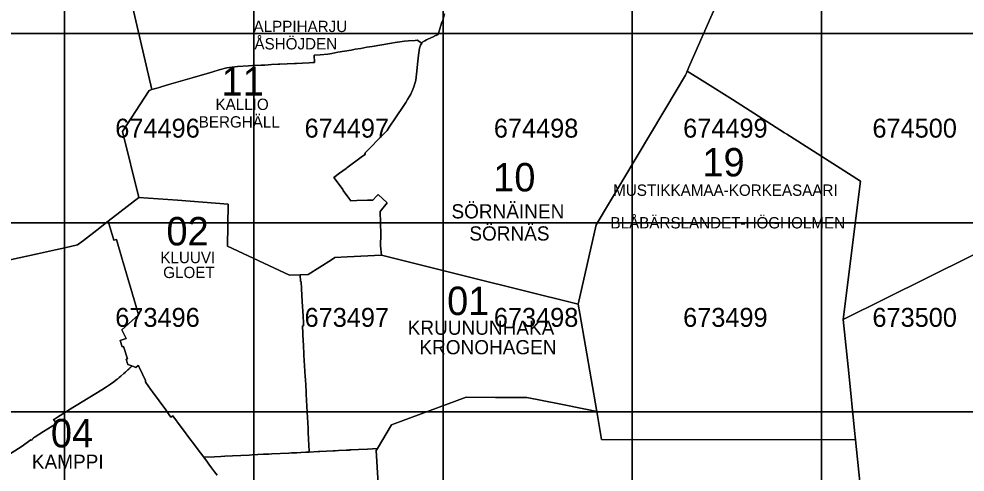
# Model space of a CAD drawing. Extents: x 25485000 to 25520000, y 6656775 to 6690000.
# Drawn here: x 25495760 to 25500758, y 6672682 to 6675077 of the extents above; entities that cross this region are included whole.
import ezdxf

# ---------------------------------------------------------------- set-up
doc = ezdxf.new("R2010")
doc.units = 0
doc.layers.add('Level 63', color=7, linetype='Continuous')

msp = doc.modelspace()

# ---------------------------------------------------------------- linework, layer by layer
at = {"layer": 'Level 63'}
for points in [[(25501089.3, 6676421.3), (25500427.3, 6676867.8), (25500377.3, 6676901.5), (25499887.6, 6676162.5), (25499782.6, 6675923.4), (25499559.7, 6675415.6), (25499304.6, 6674834.5), (25499290.4, 6674802.1), (25499383.4, 6674743.1), (25499528.4, 6674650.9), (25499804.3, 6674475.3), (25499816, 6674467.8), (25500077.8, 6674301.6), (25500206, 6674219.8), (25500113.5, 6673489.1), (25501011.9, 6673933.9)], [(25495704.9, 6673802), (25495858, 6673836.1), (25495952.7, 6673857.2), (25496001.9, 6673868.2), (25496069.3, 6673882.8), (25496101, 6673906.8), (25496170.3, 6673961.1), (25496230.7, 6674007.9), (25496393.6, 6674134.2), (25496307.3, 6674481.8), (25496447.8, 6674699.9), (25496462.5, 6674704.2), (25496263.6, 6675552.9)], [(25496263.6, 6675552.9), (25496462.5, 6674704.2), (25496507.4, 6674717.3), (25496511.4, 6674718.4), (25496551.1, 6674730), (25496674.6, 6674765.9), (25496692.2, 6674771.1), (25496749, 6674787.6), (25496783.5, 6674797.7), (25496818.1, 6674807.7), (25496858.7, 6674819.5), (25496885.4, 6674822.7), (25496914.1, 6674826.2), (25496972.5, 6674829.3), (25496993.7, 6674830.4), (25497009.8, 6674831.2), (25497039.8, 6674832.7), (25497057.8, 6674833.7), (25497093.2, 6674835.6), (25497128.7, 6674837.4), (25497138.7, 6674838), (25497215.1, 6674842), (25497225.2, 6674842.5), (25497258.1, 6674844.2), (25497292.4, 6674845.9), (25497312.4, 6674846.9), (25497321.4, 6674847.4), (25497319.5, 6674885.4), (25497351.2, 6674888.2), (25497391.9, 6674891.6), (25497411.7, 6674895.1), (25497445, 6674900.9), (25497480, 6674906.9), (25497515, 6674913), (25497536.6, 6674916.7), (25497566.2, 6674921.8), (25497597.7, 6674927.3), (25497626.3, 6674932.2), (25497727.2, 6674949.7), (25497748, 6674953), (25497772.2, 6674956.8), (25497795.7, 6674959.3), (25497817.8, 6674961.6), (25497853.5, 6674963.9), (25497863.4, 6674964.6), (25497887.7, 6674948.6), (25497890.6, 6674953), (25497892.8, 6674956.4), (25497903.2, 6674961.3), (25497913.1, 6674966.1), (25497920.4, 6674969.6), (25497947.3, 6674982.2), (25497954.6, 6674985.6), (25497953.9, 6674986.9), (25497963.9, 6674991.6), (25497964.5, 6674990.3), (25497973.7, 6674994.6), (25497980.4, 6675012), (25497992.1, 6675054.4), (25497999.1, 6675071.1), (25498008.1, 6675103.9)], [(25498008.1, 6675103.9), (25497999.1, 6675071.1), (25497992.1, 6675054.4), (25497980.4, 6675012), (25497973.7, 6674994.6), (25497964.5, 6674990.3), (25497963.9, 6674991.6), (25497953.9, 6674986.9), (25497954.6, 6674985.6), (25497947.3, 6674982.2), (25497920.4, 6674969.6), (25497913.1, 6674966.1), (25497903.2, 6674961.3), (25497892.8, 6674956.4), (25497890.6, 6674953), (25497887.7, 6674948.6), (25497881.1, 6674938.4), (25497874.9, 6674922.2), (25497871, 6674885.4), (25497867.6, 6674853.6), (25497863.9, 6674819.8), (25497861.8, 6674800.9), (25497856.8, 6674754.5), (25497853.1, 6674741.9), (25497846.2, 6674718.4), (25497842.5, 6674709.6), (25497829.7, 6674679.5), (25497812.1, 6674650.8), (25497802.7, 6674635.5), (25497792.7, 6674620.4), (25497749.2, 6674554.7), (25497716, 6674504.7), (25497704.1, 6674486.9), (25497690.7, 6674474.2), (25497585.4, 6674366.6), (25497590.2, 6674362.3), (25497567.8, 6674345.9), (25497491.9, 6674290.3), (25497487.9, 6674287.4), (25497452.4, 6674261.4), (25497423, 6674239.9), (25497440.6, 6674215.7), (25497470, 6674175.1), (25497473, 6674171.1), (25497502.6, 6674130.2), (25497512.9, 6674116), (25497545.4, 6674117), (25497600.2, 6674118.6), (25497629.8, 6674119.5), (25497649.4, 6674141.2), (25497651.6, 6674143.7), (25497657.4, 6674150.2), (25497705.7, 6674105.6), (25497668.4, 6674059.8), (25497672.2, 6673938.9), (25497670, 6673878.2), (25497675.7, 6673829), (25498139.9, 6673713.2), (25498713.4, 6673570.2), (25498808.3, 6673989.4), (25499236.9, 6674706.7), (25499269.6, 6674761.9), (25499280.3, 6674779.3), (25499284.1, 6674787.8), (25499290.4, 6674802.1), (25499304.6, 6674834.5), (25499559.7, 6675415.6)], [(25495690.6, 6672765.6), (25495771.8, 6672816.2), (25495822.9, 6672852.3), (25495827.8, 6672851), (25495829.4, 6672854), (25495830.7, 6672855.8), (25495831.6, 6672857.2), (25495832.1, 6672857.8), (25495832.8, 6672858.7), (25495833.4, 6672859.3), (25495834.2, 6672860.2), (25495834.9, 6672860.9), (25495835.8, 6672861.9), (25495836.6, 6672862.6), (25495838.4, 6672864.1), (25495839.1, 6672864.7), (25495840.1, 6672865.4), (25495841, 6672866.1), (25495841.7, 6672866.6), (25495842.1, 6672866.8), (25495842.7, 6672867.2), (25495843.6, 6672867.7), (25495844.6, 6672868.3), (25495845.5, 6672868.7), (25495889.1, 6672896.9), (25495957.6, 6672939.5), (25495942.5, 6672960.3), (25495946.6, 6672962.9), (25495963.1, 6672972.2), (25496044.2, 6673023.2), (25496061.4, 6673033.6), (25496197.7, 6673117.4), (25496222.2, 6673132.5), (25496242.5, 6673146.7), (25496261.4, 6673159.9), (25496271.4, 6673167.5), (25496278.9, 6673173.5), (25496281.3, 6673175.3), (25496283.6, 6673177.2), (25496289.3, 6673181.9), (25496297.8, 6673189), (25496313.5, 6673202.6), (25496320.8, 6673209.2), (25496323.4, 6673211.6), (25496325.6, 6673213.6), (25496335.4, 6673222.9), (25496339.7, 6673227.1), (25496340.1, 6673227.4), (25496340.7, 6673228), (25496342.3, 6673229.6), (25496345.3, 6673232.5), (25496345.5, 6673232.8), (25496345.9, 6673233.1), (25496346.4, 6673233.7), (25496350.3, 6673237.6), (25496351.4, 6673238.7), (25496352.2, 6673239.5), (25496353.5, 6673240.9), (25496354.5, 6673241.8), (25496355.5, 6673242.9), (25496355.5, 6673242.9), (25496355.9, 6673243.3), (25496334.2, 6673251.7), (25496325.8, 6673278.8), (25496332.4, 6673280.8), (25496312.2, 6673346.1), (25496305.6, 6673344.1), (25496295, 6673378.4), (25496325.6, 6673387.8), (25496303.1, 6673434.5), (25496338.3, 6673466.2), (25496390.9, 6673513.2), (25496376.7, 6673561.9), (25496310.6, 6673790), (25496305.3, 6673808), (25496275.1, 6673912), (25496260.3, 6673907.6), (25496230.7, 6674007.9), (25496170.3, 6673961.1), (25496101, 6673906.8), (25496069.3, 6673882.8), (25496001.9, 6673868.2), (25495952.7, 6673857.2), (25495858, 6673836.1), (25495704.9, 6673802)], [(25501011.9, 6673933.9), (25500113.5, 6673489.1), (25500143, 6673204.4), (25500174.3, 6672902.5), (25500179.5, 6672852.5), (25500248.5, 6672186.1), (25500288.5, 6671786.1), (25501016.8, 6671717.1)], [(25496806.3, 6672666.5), (25496793.3, 6672684), (25496777.1, 6672705.7), (25496763.4, 6672724.2), (25496754.9, 6672735.6), (25496736, 6672760.6), (25496701, 6672806.9), (25496692.2, 6672819), (25496652, 6672872.6), (25496634.2, 6672896.4), (25496616.3, 6672920.2), (25496571.8, 6672979.6), (25496562.5, 6672972.6), (25496553.5, 6672985.8), (25496535.6, 6673012.2), (25496465.1, 6673106.4), (25496454.6, 6673120.8), (25496429.1, 6673155.9), (25496427.5, 6673158.4), (25496427.9, 6673159.3), (25496428.3, 6673161), (25496428.4, 6673162.6), (25496428.3, 6673164.2), (25496427.9, 6673165.8), (25496427.5, 6673167), (25496396, 6673232.8), (25496392.1, 6673241.1), (25496389.6, 6673246.3), (25496376.3, 6673235.3), (25496355.9, 6673243.3), (25496355.5, 6673242.9), (25496355.5, 6673242.9), (25496354.5, 6673241.8), (25496353.5, 6673240.9), (25496352.2, 6673239.5), (25496351.4, 6673238.7), (25496350.3, 6673237.6), (25496346.4, 6673233.7), (25496345.9, 6673233.1), (25496345.5, 6673232.8), (25496345.3, 6673232.5), (25496342.3, 6673229.6), (25496340.7, 6673228), (25496340.1, 6673227.4), (25496339.7, 6673227.1), (25496335.4, 6673222.9), (25496325.6, 6673213.6), (25496323.4, 6673211.6), (25496320.8, 6673209.2), (25496313.5, 6673202.6), (25496297.8, 6673189), (25496289.3, 6673181.9), (25496283.6, 6673177.2), (25496281.3, 6673175.3), (25496278.9, 6673173.5), (25496271.4, 6673167.5), (25496261.4, 6673159.9), (25496242.5, 6673146.7), (25496222.2, 6673132.5), (25496197.7, 6673117.4), (25496061.4, 6673033.6), (25496044.2, 6673023.2), (25495963.1, 6672972.2), (25495946.6, 6672962.9), (25495942.5, 6672960.3), (25495957.6, 6672939.5), (25495889.1, 6672896.9), (25495845.5, 6672868.7), (25495844.6, 6672868.3), (25495843.6, 6672867.7), (25495842.7, 6672867.2), (25495842.1, 6672866.8), (25495841.7, 6672866.6), (25495841, 6672866.1), (25495840.1, 6672865.4), (25495839.1, 6672864.7), (25495838.4, 6672864.1), (25495836.6, 6672862.6), (25495835.8, 6672861.9), (25495834.9, 6672860.9), (25495834.2, 6672860.2), (25495833.4, 6672859.3), (25495832.8, 6672858.7), (25495832.1, 6672857.8), (25495831.6, 6672857.2), (25495830.7, 6672855.8), (25495829.4, 6672854), (25495827.8, 6672851), (25495822.9, 6672852.3), (25495771.8, 6672816.2), (25495690.6, 6672765.6)], [(25497661.7, 6672561.7), (25497646.7, 6672796.4), (25497653, 6672807), (25497601.8, 6672803.8), (25497553.2, 6672801.7), (25497514.4, 6672800), (25497506.3, 6672799.7), (25497506.3, 6672798.8), (25497487.9, 6672797.9), (25497448.4, 6672796.1), (25497429.8, 6672795.3), (25497420.3, 6672794.7), (25497349.2, 6672790.8), (25497341.1, 6672791), (25497293.2, 6672788.2), (25497275.5, 6672787.6), (25497248.2, 6672786.2), (25497227.9, 6672784.9), (25497200.1, 6672783.5), (25497185.9, 6672783.1), (25497094.9, 6672778.6), (25497080.6, 6672777.9), (25497051.9, 6672776.5), (25497021.9, 6672775), (25496990.9, 6672773.5), (25496976.7, 6672772.3), (25496932, 6672770.2), (25496887.3, 6672768), (25496847.1, 6672766), (25496825.5, 6672765), (25496792.7, 6672763.4), (25496736, 6672760.6), (25496754.9, 6672735.6), (25496763.4, 6672724.2), (25496777.1, 6672705.7), (25496793.3, 6672684), (25496806.3, 6672666.5)]]:
    msp.add_lwpolyline(points, dxfattribs=at)
for points in [[(25495000, 6675000), (25496000, 6675000), (25496000, 6676000), (25495000, 6676000)], [(25496000, 6675000), (25497000, 6675000), (25497000, 6676000), (25496000, 6676000)], [(25497000, 6675000), (25498000, 6675000), (25498000, 6676000), (25497000, 6676000)], [(25498000, 6675000), (25499000, 6675000), (25499000, 6676000), (25498000, 6676000)], [(25499000, 6675000), (25500000, 6675000), (25500000, 6676000), (25499000, 6676000)], [(25500000, 6675000), (25501000, 6675000), (25501000, 6676000), (25500000, 6676000)], [(25495000, 6674000), (25496000, 6674000), (25496000, 6675000), (25495000, 6675000)], [(25496000, 6674000), (25497000, 6674000), (25497000, 6675000), (25496000, 6675000)], [(25496393.6, 6674134.2), (25496597.7, 6674118.6), (25496865.3, 6674098.2), (25496861, 6673876.2), (25497188.9, 6673722.8), (25497245.7, 6673725), (25497287.9, 6673726.7), (25497410.4, 6673804.8), (25497428, 6673816), (25497494.3, 6673819.5), (25497675.7, 6673829), (25497670, 6673878.2), (25497672.2, 6673938.9), (25497668.4, 6674059.8), (25497705.7, 6674105.6), (25497657.4, 6674150.2), (25497651.6, 6674143.7), (25497649.4, 6674141.2), (25497629.8, 6674119.5), (25497600.2, 6674118.6), (25497545.4, 6674117), (25497512.9, 6674116), (25497502.6, 6674130.2), (25497473, 6674171.1), (25497470, 6674175.1), (25497440.6, 6674215.7), (25497423, 6674239.9), (25497452.4, 6674261.4), (25497487.9, 6674287.4), (25497491.9, 6674290.3), (25497567.8, 6674345.9), (25497590.2, 6674362.3), (25497585.4, 6674366.6), (25497690.7, 6674474.2), (25497704.1, 6674486.9), (25497716, 6674504.7), (25497749.2, 6674554.7), (25497792.7, 6674620.4), (25497802.7, 6674635.5), (25497812.1, 6674650.8), (25497829.7, 6674679.5), (25497842.5, 6674709.6), (25497846.2, 6674718.4), (25497853.1, 6674741.9), (25497856.8, 6674754.5), (25497861.8, 6674800.9), (25497863.9, 6674819.8), (25497867.6, 6674853.6), (25497871, 6674885.4), (25497874.9, 6674922.2), (25497881.1, 6674938.4), (25497887.7, 6674948.6), (25497863.4, 6674964.6), (25497853.5, 6674963.9), (25497817.8, 6674961.6), (25497795.7, 6674959.3), (25497772.2, 6674956.8), (25497748, 6674953), (25497727.2, 6674949.7), (25497626.3, 6674932.2), (25497597.7, 6674927.3), (25497566.2, 6674921.8), (25497536.6, 6674916.7), (25497515, 6674913), (25497480, 6674906.9), (25497445, 6674900.9), (25497411.7, 6674895.1), (25497391.9, 6674891.6), (25497351.2, 6674888.2), (25497319.5, 6674885.4), (25497321.4, 6674847.4), (25497312.4, 6674846.9), (25497292.4, 6674845.9), (25497258.1, 6674844.2), (25497225.2, 6674842.5), (25497215.1, 6674842), (25497138.7, 6674838), (25497128.7, 6674837.4), (25497093.2, 6674835.6), (25497057.8, 6674833.7), (25497039.8, 6674832.7), (25497009.8, 6674831.2), (25496993.7, 6674830.4), (25496972.5, 6674829.3), (25496914.1, 6674826.2), (25496885.4, 6674822.7), (25496858.7, 6674819.5), (25496818.1, 6674807.7), (25496783.5, 6674797.7), (25496749, 6674787.6), (25496692.2, 6674771.1), (25496674.6, 6674765.9), (25496551.1, 6674730), (25496511.4, 6674718.4), (25496507.4, 6674717.3), (25496462.5, 6674704.2), (25496447.8, 6674699.9), (25496307.3, 6674481.8)], [(25497000, 6674000), (25498000, 6674000), (25498000, 6675000), (25497000, 6675000)], [(25498000, 6674000), (25499000, 6674000), (25499000, 6675000), (25498000, 6675000)], [(25499000, 6674000), (25500000, 6674000), (25500000, 6675000), (25499000, 6675000)], [(25500000, 6674000), (25501000, 6674000), (25501000, 6675000), (25500000, 6675000)], [(25498713.4, 6673570.2), (25498722.1, 6673520.1), (25498811.9, 6673003.3), (25498837.8, 6672854.1), (25500179.5, 6672852.5), (25500174.3, 6672902.5), (25500143, 6673204.4), (25500113.5, 6673489.1), (25500206, 6674219.8), (25500077.8, 6674301.6), (25499816, 6674467.8), (25499804.3, 6674475.3), (25499528.4, 6674650.9), (25499383.4, 6674743.1), (25499290.4, 6674802.1), (25499284.1, 6674787.8), (25499280.3, 6674779.3), (25499269.6, 6674761.9), (25499236.9, 6674706.7), (25498808.3, 6673989.4)], [(25496230.7, 6674007.9), (25496260.3, 6673907.6), (25496275.1, 6673912), (25496305.3, 6673808), (25496310.6, 6673790), (25496376.7, 6673561.9), (25496390.9, 6673513.2), (25496338.3, 6673466.2), (25496303.1, 6673434.5), (25496325.6, 6673387.8), (25496295, 6673378.4), (25496305.6, 6673344.1), (25496312.2, 6673346.1), (25496332.4, 6673280.8), (25496325.8, 6673278.8), (25496334.2, 6673251.7), (25496355.9, 6673243.3), (25496376.3, 6673235.3), (25496389.6, 6673246.3), (25496392.1, 6673241.1), (25496396, 6673232.8), (25496427.5, 6673167), (25496427.9, 6673165.8), (25496428.3, 6673164.2), (25496428.4, 6673162.6), (25496428.3, 6673161), (25496427.9, 6673159.3), (25496427.5, 6673158.4), (25496429.1, 6673155.9), (25496454.6, 6673120.8), (25496465.1, 6673106.4), (25496535.6, 6673012.2), (25496553.5, 6672985.8), (25496562.5, 6672972.6), (25496571.8, 6672979.6), (25496616.3, 6672920.2), (25496634.2, 6672896.4), (25496652, 6672872.6), (25496692.2, 6672819), (25496701, 6672806.9), (25496736, 6672760.6), (25496792.7, 6672763.4), (25496825.5, 6672765), (25496847.1, 6672766), (25496887.3, 6672768), (25496932, 6672770.2), (25496976.7, 6672772.3), (25496990.9, 6672773.5), (25497021.9, 6672775), (25497051.9, 6672776.5), (25497080.6, 6672777.9), (25497094.9, 6672778.6), (25497185.9, 6672783.1), (25497200.1, 6672783.5), (25497227.9, 6672784.9), (25497248.2, 6672786.2), (25497275.5, 6672787.6), (25497293.2, 6672788.2), (25497291.2, 6672829.4), (25497290.1, 6672850.3), (25497287.8, 6672897.9), (25497286.9, 6672914.6), (25497282.5, 6672999.4), (25497277.4, 6673093.5), (25497276.6, 6673108.1), (25497272.7, 6673172.2), (25497271.7, 6673186.7), (25497265.4, 6673300.1), (25497262.3, 6673356.7), (25497261.5, 6673371.7), (25497256.9, 6673454.7), (25497263.1, 6673455), (25497262.2, 6673471), (25497260.4, 6673506.6), (25497256.6, 6673583.7), (25497253, 6673650.7), (25497251, 6673689.7), (25497247.6, 6673690), (25497245.7, 6673725), (25497188.9, 6673722.8), (25496861, 6673876.2), (25496865.3, 6674098.2), (25496597.7, 6674118.6), (25496393.6, 6674134.2)], [(25495000, 6673000), (25496000, 6673000), (25496000, 6674000), (25495000, 6674000)], [(25496000, 6673000), (25497000, 6673000), (25497000, 6674000), (25496000, 6674000)], [(25497000, 6673000), (25498000, 6673000), (25498000, 6674000), (25497000, 6674000)], [(25498000, 6673000), (25499000, 6673000), (25499000, 6674000), (25498000, 6674000)], [(25499000, 6673000), (25500000, 6673000), (25500000, 6674000), (25499000, 6674000)], [(25500000, 6673000), (25501000, 6673000), (25501000, 6674000), (25500000, 6674000)], [(25497245.7, 6673725), (25497247.6, 6673690), (25497251, 6673689.7), (25497253, 6673650.7), (25497256.6, 6673583.7), (25497260.4, 6673506.6), (25497262.2, 6673471), (25497263.1, 6673455), (25497256.9, 6673454.7), (25497261.5, 6673371.7), (25497262.3, 6673356.7), (25497265.4, 6673300.1), (25497271.7, 6673186.7), (25497272.7, 6673172.2), (25497276.6, 6673108.1), (25497277.4, 6673093.5), (25497282.5, 6672999.4), (25497286.9, 6672914.6), (25497287.8, 6672897.9), (25497290.1, 6672850.3), (25497291.2, 6672829.4), (25497293.2, 6672788.2), (25497341.1, 6672791), (25497349.2, 6672790.8), (25497420.3, 6672794.7), (25497429.8, 6672795.3), (25497448.4, 6672796.1), (25497487.9, 6672797.9), (25497506.3, 6672798.8), (25497506.3, 6672799.7), (25497514.4, 6672800), (25497553.2, 6672801.7), (25497601.8, 6672803.8), (25497653, 6672807), (25497727.9, 6672932.2), (25498122.4, 6673077.6), (25498277.7, 6673077.4), (25498384.2, 6673077.3), (25498442.7, 6673077.2), (25498613.5, 6673043), (25498761.9, 6673013.3), (25498811.9, 6673003.3), (25498722.1, 6673520.1), (25498713.4, 6673570.2), (25498139.9, 6673713.2), (25497675.7, 6673829), (25497494.3, 6673819.5), (25497428, 6673816), (25497410.4, 6673804.8), (25497287.9, 6673726.7)], [(25497653, 6672807), (25497646.7, 6672796.4), (25497661.7, 6672561.7), (25497670.7, 6672421.2), (25497800.7, 6672316.1), (25497957.8, 6672188.9), (25498158.3, 6672188.6), (25500248.5, 6672186.1), (25500179.5, 6672852.5), (25498837.8, 6672854.1), (25498811.9, 6673003.3), (25498761.9, 6673013.3), (25498613.5, 6673043), (25498442.7, 6673077.2), (25498384.2, 6673077.3), (25498277.7, 6673077.4), (25498122.4, 6673077.6), (25497727.9, 6672932.2)], [(25495000, 6672000), (25496000, 6672000), (25496000, 6673000), (25495000, 6673000)], [(25496000, 6672000), (25497000, 6672000), (25497000, 6673000), (25496000, 6673000)], [(25497000, 6672000), (25498000, 6672000), (25498000, 6673000), (25497000, 6673000)], [(25498000, 6672000), (25499000, 6672000), (25499000, 6673000), (25498000, 6673000)], [(25499000, 6672000), (25500000, 6672000), (25500000, 6673000), (25499000, 6673000)], [(25500000, 6672000), (25501000, 6672000), (25501000, 6673000), (25500000, 6673000)]]:
    msp.add_lwpolyline(points, close=True, dxfattribs=at)

# ---------------------------------------------------------------- texts
for s, height, p in [('ALPPIHARJU', 60, (25496998.9, 6675007.8)), ('ÅSHÖJDEN', 60, (25497003.7, 6674916.1)), ('11', 150, (25496829.9, 6674672.4)), ('KALLIO', 60, (25496798.1, 6674596)), ('BERGHÄLL', 60, (25496709.5, 6674503.1)), ('674496', 100, (25496268.5, 6674450)), ('674497', 100, (25497268.5, 6674450)), ('674498', 100, (25498268.5, 6674450)), ('674499', 100, (25499268.5, 6674450)), ('674500', 100, (25500268.5, 6674450)), ('19', 150, (25499370.3, 6674245.1)), ('10', 150, (25498265, 6674165.7)), ('MUSTIKKAMAA-KORKEASAARI', 60, (25498898.8, 6674142.3)), ('SÖRNÄINEN', 75, (25498044.5, 6674023)), ('02', 150, (25496538.9, 6673880.4)), ('BLÅBÄRSLANDET-HÖGHOLMEN', 60, (25498884.7, 6673970)), ('SÖRNÄS', 75, (25498139, 6673906.1)), ('KLUUVI', 60, (25496506.7, 6673786.5)), ('GLOET', 60, (25496521.6, 6673707.7)), ('01', 150, (25498021.6, 6673512.4)), ('673496', 100, (25496268.5, 6673450)), ('673497', 100, (25497268.5, 6673450)), ('673498', 100, (25498268.5, 6673450)), ('673499', 100, (25499268.5, 6673450)), ('673500', 100, (25500268.5, 6673450)), ('KRUUNUNHAKA', 75, (25497813.3, 6673408)), ('KRONOHAGEN', 75, (25497875.2, 6673305)), ('04', 150, (25495928.4, 6672813.2)), ('KAMPPI', 75, (25495827.9, 6672699.7))]:
    msp.add_text(s, height=height, dxfattribs=at).set_placement(p)

doc.saveas('drawing.dxf')
